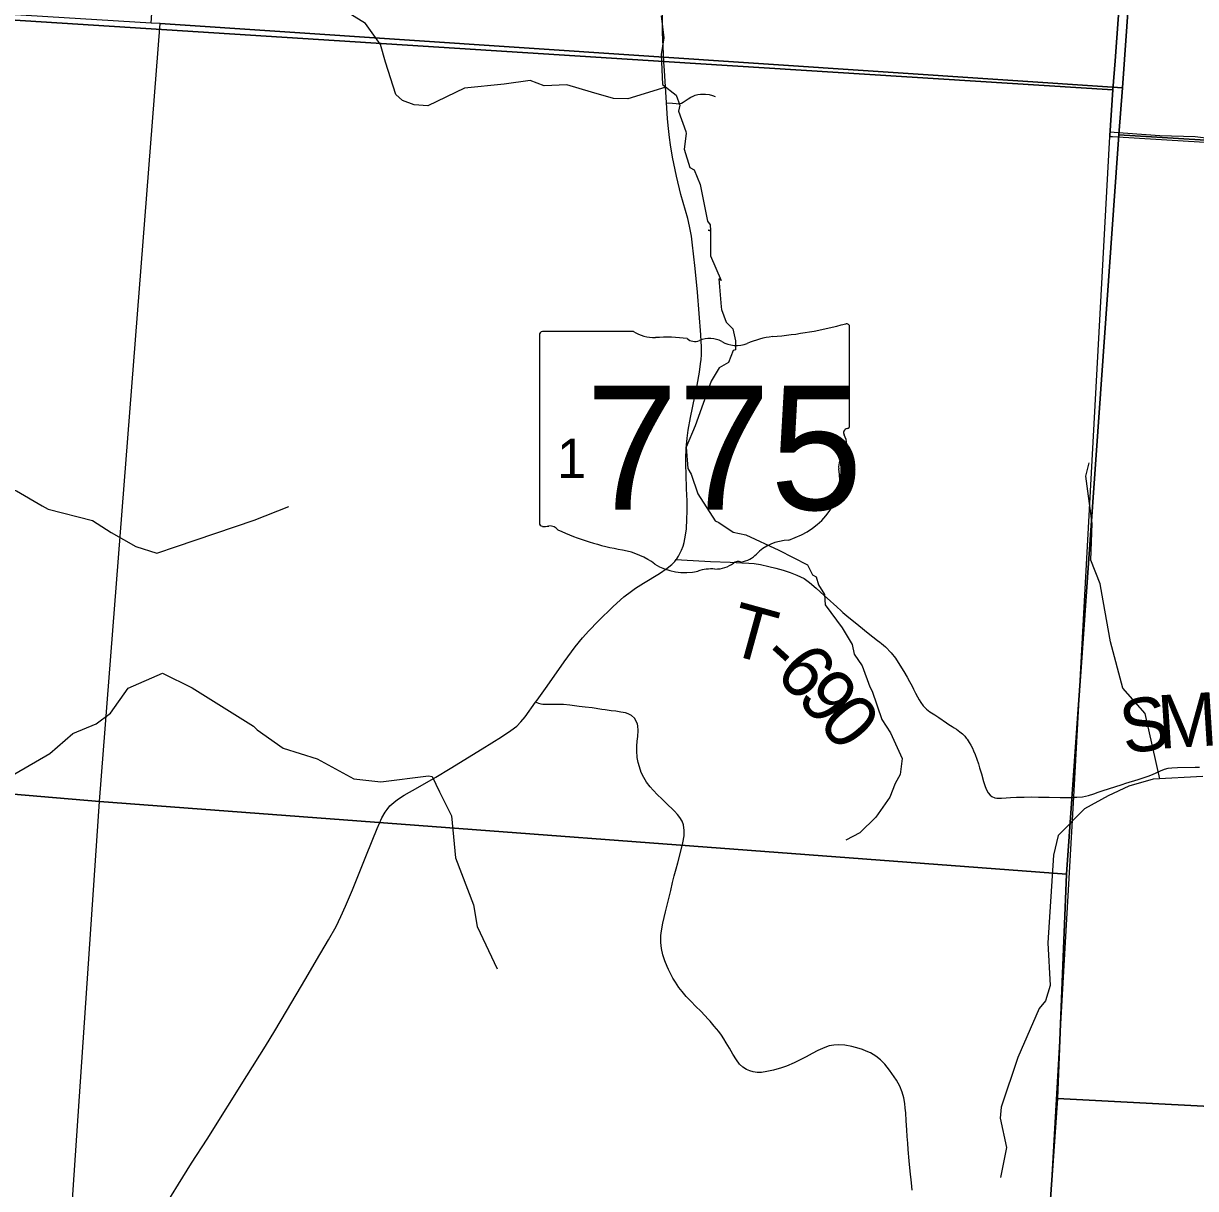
# Model space of a CAD drawing. Extents: x 396.2 to 468.4, y 232.6 to 279.1.
# Drawn here: x 414.49 to 415.736, y 275.483 to 276.722 of the extents above; entities that cross this region are included whole.
import ezdxf

# ---------------------------------------------------------------- set-up
doc = ezdxf.new("R2010")
doc.units = 0
for name, color, linetype in [('Default', 7, 'Continuous'), ('GM_X_County_Road', 7, 'Continuous'), ('GM_X_Minor_River', 7, 'Continuous'), ('GM_X_Section', 7, 'Continuous'), ('GM_X_Section_Text', 7, 'Continuous'), ('GM_X_State_Location', 7, 'Continuous'), ('GM_X_State_Route', 7, 'Continuous'), ('GM_X_State_Shield', 7, 'Continuous'), ('GM_X_Township', 7, 'Continuous'), ('GM_X_Township_Road', 7, 'Continuous'), ('GM_X_Township_Road_Text', 7, 'Continuous')]:
    doc.layers.add(name, color=color, linetype=linetype)

msp = doc.modelspace()

# ---------------------------------------------------------------- linework, layer by layer
at = {"layer": 'Default'}
for points in [[(415.7353, 277.8582), (413.8513, 277.8582), (413.8513, 276.7667), (414.1803, 276.7441), (415.1704, 276.681), (415.6478, 276.651), (415.6501, 276.6818), (415.7264, 277.732)], [(413.8513, 276.7696), (413.8513, 275.9557), (414.5706, 275.8945), (414.6352, 276.7213), (414.6257, 276.7217)], [(413.8513, 275.9557), (413.8513, 274.9056), (414.5003, 274.8549), (414.5706, 275.8945)]]:
    msp.add_lwpolyline(points, close=True, dxfattribs=at)
for points in [[(415.7264, 277.732), (415.6501, 276.6818), (415.6478, 276.651), (415.6445, 276.6023), (415.6444, 276.6015), (415.6473, 276.6014), (415.676, 276.5996), (416.0069, 276.5795)], [(415.3087, 271.617), (415.3585, 272.2209), (415.4595, 273.6806), (415.4838, 274.0061), (415.5736, 275.3305), (415.6062, 275.8993), (415.6444, 276.6015), (415.6445, 276.6023), (415.6478, 276.651), (415.1704, 276.681), (414.1803, 276.7441), (413.8513, 276.7667), (413.8513, 270.6726)]]:
    msp.add_lwpolyline(points, dxfattribs=at)
at = {"layer": 'GM_X_County_Road'}
msp.add_lwpolyline([(415.4343, 275.4813), (415.4335, 275.4891), (415.4323, 275.5015), (415.4313, 275.5124), (415.4302, 275.5244), (415.4296, 275.5312), (415.4291, 275.5385), (415.4286, 275.5455), (415.4281, 275.555), (415.4276, 275.5634), (415.4271, 275.5685), (415.4266, 275.5733), (415.4255, 275.5794), (415.4238, 275.5854), (415.4212, 275.5917), (415.4176, 275.5982), (415.4129, 275.6055), (415.4104, 275.609), (415.4054, 275.6151), (415.4007, 275.62), (415.3959, 275.6238), (415.39, 275.6272), (415.3854, 275.6292), (415.3817, 275.6307), (415.3779, 275.6319), (415.3701, 275.6341), (415.3627, 275.6354), (415.3565, 275.6358), (415.351, 275.6355), (415.3461, 275.6346), (415.3414, 275.6331), (415.3341, 275.6297), (415.3281, 275.6266), (415.3217, 275.6231), (415.3138, 275.6192), (415.3091, 275.6167), (415.3007, 275.6132), (415.2954, 275.6114), (415.2871, 275.6089), (415.2798, 275.6073), (415.2742, 275.6065), (415.2696, 275.6064), (415.2653, 275.6071), (415.2618, 275.608), (415.2584, 275.6096), (415.2544, 275.6119), (415.2509, 275.6153), (415.2475, 275.6199), (415.2437, 275.626), (415.2403, 275.6323), (415.2367, 275.6381), (415.2342, 275.642), (415.2316, 275.6459), (415.2289, 275.65), (415.224, 275.6556), (415.2197, 275.6609), (415.2176, 275.6632), (415.21, 275.6713), (415.2042, 275.6769), (415.1994, 275.6818), (415.1942, 275.6871), (415.1899, 275.6924), (415.1864, 275.6968), (415.1827, 275.7025), (415.1801, 275.7067), (415.1775, 275.7116), (415.1753, 275.716), (415.174, 275.7189), (415.1714, 275.7252), (415.1693, 275.7316), (415.168, 275.7383), (415.1673, 275.7445), (415.1674, 275.7519), (415.1678, 275.7568), (415.1694, 275.7652), (415.1723, 275.7772), (415.1759, 275.7915), (415.1778, 275.8), (415.1798, 275.8084), (415.1815, 275.8155), (415.1834, 275.8229), (415.1852, 275.8292), (415.1883, 275.8402), (415.1907, 275.8505), (415.1919, 275.8578), (415.1921, 275.8635), (415.1914, 275.8696), (415.1898, 275.8736), (415.1876, 275.8773), (415.1849, 275.8806), (415.1816, 275.8843), (415.1727, 275.893), (415.1683, 275.8973), (415.1638, 275.9016), (415.1591, 275.9065), (415.1558, 275.9102), (415.152, 275.9151), (415.1492, 275.9198), (415.1465, 275.9254), (415.1445, 275.9313), (415.1431, 275.936), (415.1422, 275.9414), (415.1416, 275.9482), (415.1417, 275.9532), (415.1422, 275.9586), (415.1427, 275.9637), (415.1432, 275.9698), (415.1429, 275.9748), (415.1424, 275.9766), (415.1411, 275.98), (415.1391, 275.9831), (415.1359, 275.986), (415.1326, 275.9876), (415.1297, 275.9886), (415.1248, 275.9895), (415.1193, 275.9903), (415.1144, 275.9909), (415.1082, 275.9918), (415.1045, 275.9923), (415.0941, 275.9939), (415.0868, 275.9948), (415.0806, 275.9956), (415.0707, 275.9969), (415.0639, 275.9975), (415.0565, 275.9977), (415.0528, 275.9976), (415.0488, 275.9975), (415.0454, 275.9974), (415.0419, 275.9977), (415.0399, 275.9979), (415.0376, 275.9986), (415.0341, 276.0001)], dxfattribs=at)
at = {"layer": 'GM_X_Minor_River'}
for points in [[(415.1725, 276.6538), (415.1321, 276.6413), (415.117, 276.6417), (415.0935, 276.6485), (415.0673, 276.6561), (415.0434, 276.6553), (415.0283, 276.661), (415.0006, 276.6568), (414.9585, 276.6526), (414.9195, 276.6339), (414.9051, 276.635), (414.8926, 276.6396), (414.8857, 276.646), (414.8747, 276.6802), (414.8694, 276.6992), (414.8532, 276.7213), (414.8217, 276.741)], [(415.1675, 276.7295), (415.1705, 276.7063), (415.1677, 276.6885)], [(415.1677, 276.6885), (415.1689, 276.6566), (415.1834, 276.6453), (415.1874, 276.6348), (415.1859, 276.6283), (415.1938, 276.6067), (415.1942, 276.6044), (415.1922, 276.5877), (415.1981, 276.5684), (415.2027, 276.5658), (415.209, 276.5503), (415.2167, 276.5113), (415.2198, 276.5075), (415.2199, 276.5014), (415.2176, 276.5018), (415.2199, 276.5011), (415.2202, 276.4745), (415.2312, 276.4484), (415.2289, 276.4499), (415.2312, 276.4203), (415.2316, 276.4173), (415.2367, 276.404), (415.2436, 276.3969), (415.2465, 276.384), (415.2466, 276.3745), (415.2443, 276.3737), (415.2392, 276.3612), (415.2294, 276.3554), (415.2208, 276.3413), (415.2036, 276.2937), (415.194, 276.2712), (415.1959, 276.2484), (415.1994, 276.2424), (415.2065, 276.2216), (415.2251, 276.1929), (415.2289, 276.191), (415.2442, 276.1809), (415.2575, 276.178), (415.2927, 276.1616), (415.3232, 276.1459), (415.3283, 276.1354), (415.3325, 276.1331), (415.3349, 276.1248), (415.3411, 276.1146), (415.342, 276.1036), (415.3598, 276.0791), (415.3707, 276.0613), (415.3727, 276.0511), (415.3812, 276.0387), (415.3895, 276.0163), (415.3918, 276.0118), (415.4021, 275.9815), (415.4114, 275.9676), (415.4239, 275.94), (415.4215, 275.9233), (415.4163, 275.9137), (415.4108, 275.8989), (415.3959, 275.8779), (415.3786, 275.861), (415.3639, 275.8533)], [(415.786, 276.5945), (415.7352, 276.6009), (415.6977, 276.602), (415.6442, 276.6061)], [(414.101, 276.3818), (414.1681, 276.4305), (414.2048, 276.4259), (414.2431, 276.4237), (414.2803, 276.4165), (414.3303, 276.4006), (414.353, 276.3903), (414.3936, 276.363), (414.4023, 276.3516), (414.4133, 276.3261), (414.422, 276.2756), (414.4364, 276.2524), (414.4656, 276.2304), (414.4826, 276.2247), (414.5099, 276.2088), (414.516, 276.2053), (414.5633, 276.1932), (414.5831, 276.1803), (414.6092, 276.1655), (414.6316, 276.1583), (414.6524, 276.1656), (414.7351, 276.1934), (414.7718, 276.2079)], [(415.6975, 275.9187), (415.6819, 275.9879), (415.6584, 276.0149), (415.6452, 276.0643), (415.6372, 276.1076), (415.6342, 276.1259), (415.6244, 276.151), (415.6255, 276.1901), (415.6191, 276.2403), (415.6225, 276.2544)], [(414.4696, 275.9175), (414.5178, 275.9453), (414.5424, 275.9666), (414.5671, 275.9769), (414.5822, 275.9883), (414.6012, 276.0149), (414.6376, 276.031), (414.669, 276.0154), (414.7342, 275.9744), (414.7384, 275.9706), (414.7657, 275.9512), (414.8021, 275.9399), (414.8411, 275.9186), (414.8695, 275.9152), (414.9203, 275.9217), (414.9241, 275.921), (414.9321, 275.9046), (414.9446, 275.8792), (414.9491, 275.8347), (414.9681, 275.7845), (414.9722, 275.7617), (414.9934, 275.7165)], [(415.7433, 275.9211), (415.6906, 275.9183), (415.6648, 275.9107), (415.6428, 275.9004), (415.6174, 275.8867), (415.5894, 275.8582), (415.5844, 275.8373), (415.5787, 275.7441), (415.581, 275.6989), (415.5761, 275.6825), (415.5692, 275.6745)], [(415.5692, 275.6745), (415.5466, 275.6223), (415.5291, 275.5697), (415.528, 275.5579), (415.5346, 275.5266), (415.5283, 275.4949)]]:
    msp.add_lwpolyline(points, dxfattribs=at)
at = {"layer": 'GM_X_Section'}
for points in [[(415.7301, 277.667), (415.7271, 277.6318), (415.6579, 276.653), (414.6352, 276.7213), (414.6257, 276.7217), (414.6945, 277.744)], [(415.7271, 277.6318), (416.7426, 277.5691), (416.6739, 276.5403), (415.6539, 276.603), (415.6579, 276.653)], [(415.6579, 276.653), (415.6539, 276.603), (415.5983, 275.8171), (414.5706, 275.8945), (414.6352, 276.7213)], [(415.6539, 276.603), (416.6739, 276.5403), (416.6066, 275.5251), (415.5888, 275.5786), (415.5983, 275.8171)], [(414.5706, 275.8945), (415.5983, 275.8171), (415.5888, 275.5786), (415.5344, 274.7946), (414.5003, 274.8549)], [(415.5888, 275.5786), (416.6066, 275.5251), (416.5371, 274.5285), (415.5204, 274.5839), (415.5344, 274.7946)]]:
    msp.add_lwpolyline(points, close=True, dxfattribs=at)
at = {"layer": 'GM_X_State_Route'}
for points in [[(415.1706, 276.6804), (415.1696, 276.6969), (415.1689, 276.7118), (415.1689, 276.7444)], [(414.6335, 275.4534), (414.6686, 275.5099), (414.685, 275.5355), (414.7274, 275.6027), (414.7471, 275.6343), (414.7571, 275.6507), (414.7695, 275.6716), (414.7899, 275.7064), (414.8012, 275.7257), (414.8142, 275.7475), (414.8222, 275.7616), (414.8273, 275.7723), (414.8321, 275.7831), (414.8395, 275.8006), (414.8544, 275.8376), (414.8656, 275.8657), (414.8708, 275.8772), (414.8743, 275.883), (414.8763, 275.886), (414.8794, 275.89), (414.8834, 275.8934), (414.8874, 275.8965), (414.8945, 275.9013), (414.9091, 275.9095), (414.928, 275.9203), (414.9435, 275.9296), (414.9772, 275.9506), (414.9978, 275.9633), (415.008, 275.9698), (415.0142, 275.9746), (415.0184, 275.9791), (415.0229, 275.9846), (415.0341, 276.0001), (415.0357, 276.0023), (415.0463, 276.017), (415.0646, 276.0428), (415.0763, 276.0588), (415.084, 276.0685), (415.0906, 276.0759), (415.1005, 276.0861), (415.1166, 276.1016), (415.1281, 276.1119), (415.1359, 276.118), (415.1404, 276.1212), (415.1487, 276.1265), (415.1658, 276.1368), (415.1741, 276.1424), (415.1789, 276.1465), (415.182, 276.1496), (415.1836, 276.1516), (415.1844, 276.1525), (415.1862, 276.1552), (415.1893, 276.1615), (415.191, 276.166), (415.1922, 276.1699), (415.1935, 276.1775), (415.1944, 276.1844), (415.195, 276.1944), (415.1951, 276.203), (415.1951, 276.214), (415.1947, 276.2268), (415.194, 276.2425), (415.1938, 276.2522), (415.1937, 276.259), (415.1941, 276.2697), (415.1951, 276.2807), (415.1964, 276.2893), (415.1988, 276.3025), (415.2057, 276.3369), (415.2082, 276.3507), (415.2095, 276.3597), (415.21, 276.3644), (415.2103, 276.3693), (415.2104, 276.3774), (415.2097, 276.3904), (415.2062, 276.436), (415.2039, 276.4611), (415.2021, 276.4765), (415.201, 276.4857), (415.1997, 276.4954), (415.1977, 276.5059), (415.1959, 276.5142), (415.1885, 276.5396), (415.1838, 276.5592), (415.1798, 276.5793), (415.1775, 276.5926), (415.1764, 276.6002), (415.1751, 276.6131), (415.1745, 276.6204), (415.1733, 276.6371), (415.1712, 276.6716), (415.1706, 276.6804)]]:
    msp.add_lwpolyline(points, dxfattribs=at)
at = {"layer": 'GM_X_State_Shield'}
for p, q in [((415.0383, 276.3905), (415.0383, 276.1904)), ((415.1381, 276.394), (415.0415, 276.394)), ((415.3679, 276.2942), (415.3679, 276.3989)), ((415.3678, 276.2943), (415.3679, 276.2942))]:
    msp.add_line(p, q, dxfattribs=at)
for centre, major_axis, start_param, end_param in [((415.2505, 276.6668), (0.3495, 0), 4.814394, 5.042369), ((415.3642, 276.3994), (0.00367, 0), 6.141152, 7.989035), ((415.0421, 276.3909), (0.00382, 0), 1.712693, 3.28349), ((415.161, 276.4172), (0.037, 0), 4.042523, 4.731795), ((415.1733, 276.2816), (0.133, 0), 1.404758, 1.657858), ((415.2035, 276.392), (0.0107, 0), 3.836095, 5.185415), ((415.2192, 276.3689), (0.0222, 0), 0.950623, 2.079405), ((415.2479, 276.4006), (0.0267, 0), 4.081561, 5.145723), ((415.2951, 276.3328), (0.0703, 0), 1.699011, 2.107814), ((415.367, 276.2866), (0.00568, 0), 1.883978, 3.671073), ((415.364, 276.2938), (0.00393, 0), 5.05454, 6.418171), ((415.3309, 276.2733), (0.0341, 0), 5.934695, 6.695948), ((415.381, 276.2504), (0.0248, 0), 2.387724, 3.262537), ((415.2701, 276.2371), (0.0874, 0), 5.101752, 6.440018), ((415.0421, 276.19), (0.00385, 0), 3.00124, 4.508301), ((415.0427, 276.2104), (0.0294, 0), 4.665946, 4.897461), ((415.0487, 276.1789), (0.0106, 0), 0.519207, 1.627899), ((415.1825, 276.3587), (0.2524, 0), 4.195997, 4.488961), ((415.3069, 276.1342), (0.0479, 0), 1.647645, 2.488434), ((415.1073, 276.1005), (0.079, 0), 0.823519, 1.323587), ((415.2463, 276.171), (0.0282, 0), 4.937069, 5.64225), ((415.1927, 276.1779), (0.0501, 0), 4.026481, 4.996735), ((415.2216, 276.1087), (0.0412, 0), 1.495662, 1.94098), ((415.2253, 276.1629), (0.0267, 0), 4.691044, 5.507374), ((415.2495, 276.1435), (0.00752, 0), 1.147584, 2.315152)]:
    msp.add_ellipse(centre, major_axis=major_axis, ratio=0.8, start_param=start_param, end_param=end_param, dxfattribs=at)
at = {"layer": 'GM_X_Township'}
msp.add_lwpolyline([(415.3087, 271.617), (415.3585, 272.2209), (415.4595, 273.6806), (415.4838, 274.0061), (415.5736, 275.3305), (415.6062, 275.8993), (415.6444, 276.6015), (415.6473, 276.6014), (415.676, 276.5996), (416.0069, 276.5795)], dxfattribs=at)
at = {"layer": 'GM_X_Township_Road'}
for points in [[(415.1733, 276.6371), (415.1797, 276.6366), (415.1834, 276.6363), (415.1855, 276.6361), (415.1874, 276.6363), (415.1891, 276.6367), (415.191, 276.6377), (415.1931, 276.6392), (415.1962, 276.6414), (415.1992, 276.6432), (415.2015, 276.6443), (415.2038, 276.6451), (415.2066, 276.6459), (415.2095, 276.6464), (415.2122, 276.6465), (415.2148, 276.6464), (415.2185, 276.6459), (415.222, 276.645), (415.2251, 276.6438)], [(415.1836, 276.1516), (415.1892, 276.1513), (415.22, 276.1495), (415.2411, 276.1489), (415.2534, 276.1482), (415.2607, 276.1479), (415.2664, 276.1475), (415.2731, 276.1465), (415.2821, 276.1444), (415.2896, 276.1424), (415.2973, 276.1402), (415.3048, 276.1379), (415.3119, 276.1351), (415.3195, 276.1314), (415.3253, 276.1273), (415.3325, 276.1211), (415.3408, 276.1134), (415.3441, 276.1105), (415.3542, 276.1013), (415.3588, 276.0972), (415.3606, 276.0955), (415.3648, 276.0918), (415.3776, 276.0814), (415.3877, 276.0735), (415.3975, 276.0657), (415.4001, 276.0637), (415.4018, 276.0623), (415.4059, 276.0587), (415.4119, 276.0524), (415.4166, 276.0467), (415.4214, 276.0395), (415.4255, 276.0327), (415.429, 276.0267), (415.4316, 276.022), (415.4343, 276.0169), (415.4359, 276.0138), (415.4379, 276.0097), (415.4401, 276.0057), (415.4417, 276.0025), (415.4434, 275.9997), (415.4459, 275.9962), (415.4495, 275.9925), (415.4531, 275.9898), (415.4584, 275.9866), (415.4626, 275.9838), (415.4709, 275.9781), (415.4734, 275.9764), (415.477, 275.9742), (415.479, 275.9729), (415.4815, 275.9712), (415.485, 275.9686), (415.4879, 275.9664), (415.4904, 275.9638), (415.4919, 275.9619), (415.4927, 275.9606), (415.4951, 275.9571), (415.4967, 275.9543), (415.4984, 275.9513), (415.4997, 275.9482), (415.5013, 275.9445), (415.5031, 275.9395), (415.5048, 275.9346), (415.5061, 275.9301), (415.5081, 275.9238), (415.5102, 275.9156), (415.5119, 275.9104), (415.5133, 275.9068), (415.515, 275.9036), (415.5172, 275.9013), (415.5192, 275.8997), (415.5221, 275.8984), (415.5245, 275.898), (415.5294, 275.8979), (415.5341, 275.8983), (415.5387, 275.8986), (415.5454, 275.8991), (415.5535, 275.8991), (415.5615, 275.8993), (415.5687, 275.8992), (415.5801, 275.8991), (415.5918, 275.8987), (415.6018, 275.8986), (415.6064, 275.8988), (415.6074, 275.8989)], [(415.6074, 275.8989), (415.6093, 275.899), (415.6155, 275.8995), (415.6218, 275.9007), (415.6274, 275.9025), (415.6322, 275.9043), (415.6374, 275.9061), (415.6498, 275.9101), (415.6574, 275.9125), (415.6616, 275.9138), (415.6746, 275.9178), (415.6788, 275.9191), (415.6821, 275.9203), (415.6864, 275.9218), (415.6905, 275.9234), (415.6929, 275.9246), (415.6983, 275.9272), (415.7027, 275.9289), (415.7064, 275.9298), (415.7103, 275.9303), (415.7165, 275.9307), (415.7353, 275.9309), (415.7397, 275.9311)]]:
    msp.add_lwpolyline(points, dxfattribs=at)

# ---------------------------------------------------------------- texts
at = {"layer": 'GM_X_Section_Text'}
msp.add_text('1', height=0.0419, rotation=0, dxfattribs=at).set_placement((415.0567, 276.2382))
at = {"layer": 'GM_X_State_Location'}
for s in ['s', 'r']:
    msp.add_text(s, height=0.000189, dxfattribs=at).set_placement((415.1994, 276.2772))
msp.add_text('775', height=0.000189, rotation=0, dxfattribs=at).set_placement((415.1325, 276.2634))
at = {"layer": 'GM_X_State_Shield'}
msp.add_text('775', height=0.13184, dxfattribs=at).set_placement((415.0874, 276.2045))
at = {"layer": 'GM_X_Township_Road_Text'}
for s, rotation, p in [('T', 344.5989, (415.236, 276.0522)), ('-', 317.7885, (415.2708, 276.0443)), ('6', 312.4694, (415.2871, 276.0296)), ('9', 310.5355, (415.3104, 276.0041)), ('0', 310.1794, (415.3331, 275.9776)), ('S', 9.5592, (415.6606, 275.9442)), ('M', 3.5688, (415.6969, 275.9504))]:
    msp.add_text(s, height=0.0568, rotation=rotation, dxfattribs=at).set_placement(p)

doc.saveas('drawing.dxf')
